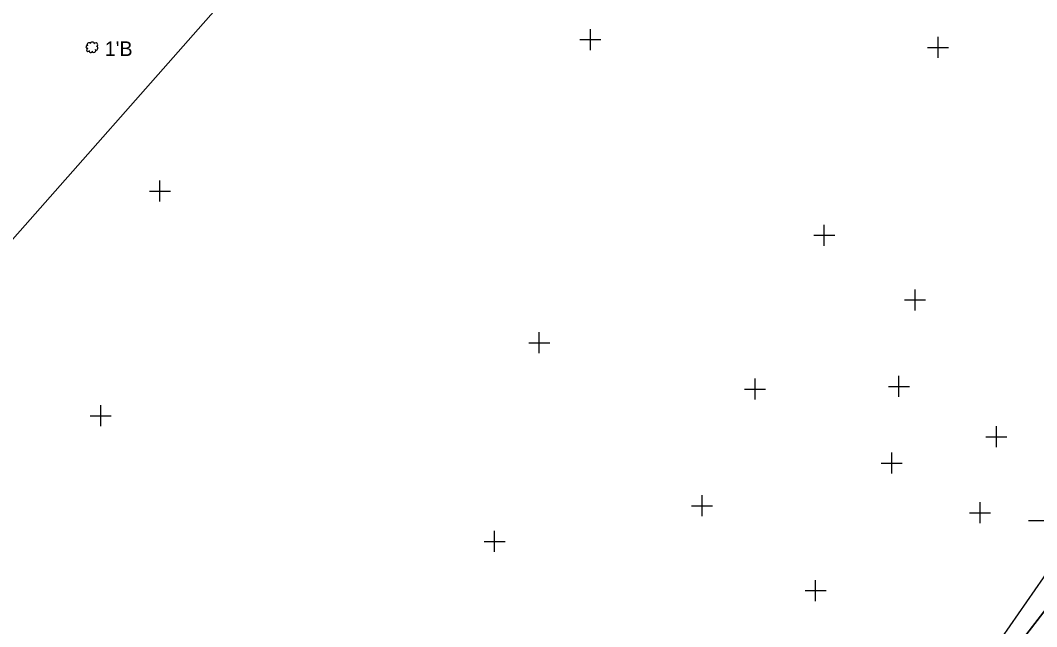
# Model space of a CAD drawing. Extents: x 1324236 to 1326110, y 459090 to 460782.
# Drawn here: x 1325160.4 to 1325257.3, y 460246.1 to 460303.9 of the extents above; entities that cross this region are included whole.
import ezdxf

# ---------------------------------------------------------------- set-up
doc = ezdxf.new("R2010")
doc.units = 0
for name, color, linetype in [('DR_X_Ditch', 7, 'Continuous'), ('E-RW-ODOT', 7, 'Continuous'), ('PM_X_Misc', 7, 'Continuous'), ('RW_X_CL', 7, 'Continuous'), ('VG_X_Cells', 7, 'Continuous')]:
    doc.layers.add(name, color=color, linetype=linetype)

msp = doc.modelspace()

# ---------------------------------------------------------------- linework, layer by layer
at = {"layer": 'DR_X_Ditch'}
msp.add_line((1325268.795, 460261.453), (1325251.495, 460239.074), dxfattribs=at)
msp.add_lwpolyline([(1325301.567, 460318.507), (1325302.382, 460311.139), (1325300.564, 460306.589), (1325287.218, 460286.49), (1325268.795, 460261.453), (1325251.495, 460239.074), (1325233.127, 460213.119), (1325215.709, 460188.927), (1325205.669, 460177.311)], dxfattribs=at)
at = {"layer": 'E-RW-ODOT'}
msp.add_line((1325084.273, 460197.503), (1325254.991, 460391.136), dxfattribs=at)
at = {"layer": 'PM_X_Misc'}
msp.add_line((1325266.923, 460263.729), (1325250.322, 460239.748), dxfattribs=at)
at = {"layer": 'RW_X_CL'}
for p, q in [((1325214.758, 460301.053), (1325214.758, 460303.053)), ((1325213.758, 460302.053), (1325215.758, 460302.053)), ((1325247.921, 460300.297), (1325247.921, 460302.297)), ((1325246.921, 460301.297), (1325248.921, 460301.297)), ((1325173.707, 460286.598), (1325173.707, 460288.598)), ((1325172.707, 460287.598), (1325174.707, 460287.598)), ((1325237.058, 460282.386), (1325237.058, 460284.386)), ((1325236.058, 460283.386), (1325238.058, 460283.386)), ((1325245.726, 460276.228), (1325245.726, 460278.228)), ((1325244.726, 460277.228), (1325246.726, 460277.228)), ((1325209.887, 460272.145), (1325209.887, 460274.145)), ((1325208.887, 460273.145), (1325210.887, 460273.145)), ((1325230.469, 460267.714), (1325230.469, 460269.714)), ((1325244.188, 460267.971), (1325244.188, 460269.971)), ((1325229.469, 460268.714), (1325231.469, 460268.714)), ((1325243.188, 460268.971), (1325245.188, 460268.971)), ((1325168.058, 460265.178), (1325168.058, 460267.178)), ((1325167.058, 460266.178), (1325169.058, 460266.178)), ((1325253.479, 460263.183), (1325253.479, 460265.183)), ((1325252.479, 460264.183), (1325254.479, 460264.183)), ((1325243.493, 460260.671), (1325243.493, 460262.671)), ((1325242.493, 460261.67), (1325244.493, 460261.67)), ((1325225.415, 460256.599), (1325225.415, 460258.599)), ((1325251.919, 460255.934), (1325251.919, 460257.934)), ((1325224.415, 460257.599), (1325226.415, 460257.599)), ((1325250.919, 460256.934), (1325252.919, 460256.934)), ((1325256.547, 460256.2), (1325258.547, 460256.2)), ((1325205.625, 460253.19), (1325205.625, 460255.19)), ((1325204.625, 460254.19), (1325206.625, 460254.19)), ((1325236.234, 460248.507), (1325236.234, 460250.507)), ((1325235.234, 460249.508), (1325237.234, 460249.508))]:
    msp.add_line(p, q, dxfattribs=at)
at = {"layer": 'VG_X_Cells'}
for centre, radius, start, end in [((1325166.96, 460301.533), 0.216, 47.72631, 199.65382), ((1325167.25, 460301.606), 0.205, 8.1301, 171.8699), ((1325167.57, 460301.519), 0.209, 303.69007, 146.30993), ((1325166.815, 460301.344), 0.174, 90, 270), ((1325166.854, 460301.076), 0.157, 104.48976, 329.25003), ((1325167.109, 460300.989), 0.178, 177.66269, 343.41266), ((1325167.403, 460301.011), 0.195, 201.80141, 31.32869), ((1325167.59, 460301.232), 0.195, 246.16126, 60.70864)]:
    msp.add_arc(centre, radius, start, end, dxfattribs=at)

# ---------------------------------------------------------------- texts
msp.add_text("1'B", height=1.4, dxfattribs=at).set_placement((1325168.446, 460300.481))

doc.saveas('drawing.dxf')
